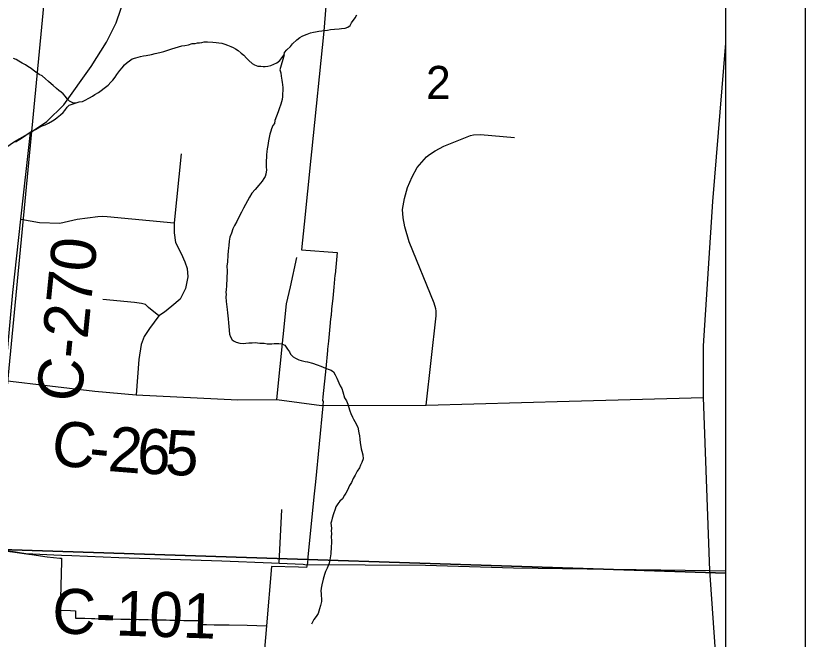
# Model space of a CAD drawing. Extents: x 0 to 34, y -3.9 to 26.2.
# Drawn here: x 8.005 to 9, y 17.653 to 18.439 of the extents above; entities that cross this region are included whole.
import ezdxf

# ---------------------------------------------------------------- set-up
doc = ezdxf.new("R2010")
doc.units = 0
for name, color, linetype in [('GM_X_City_Street', 7, 'Continuous'), ('GM_X_Corporation', 7, 'Continuous'), ('GM_X_County_Road', 7, 'Continuous'), ('GM_X_County_Road_Text', 7, 'Continuous'), ('GM_X_Interchange_Ramps', 7, 'Continuous'), ('GM_X_Interstate_Route', 7, 'Continuous'), ('GM_X_Minor_River', 7, 'Continuous'), ('GM_X_Section', 7, 'Continuous'), ('GM_X_Section_Text', 7, 'Continuous'), ('GM_X_State_Route', 7, 'Continuous'), ('GM_X_State_Shield', 7, 'Continuous'), ('GM_X_Township_Road', 7, 'Continuous'), ('GM_X_US_Route', 7, 'Continuous'), ('SH_Data', 7, 'Continuous')]:
    doc.layers.add(name, color=color, linetype=linetype)

msp = doc.modelspace()

# ---------------------------------------------------------------- linework, layer by layer
at = {"layer": 'GM_X_City_Street'}
for points in [[(8.84586, 17.14096), (8.85864, 17.29642), (8.87165, 17.44975), (8.88717, 17.59506), (8.8882, 17.61025), (8.88771, 17.62546), (8.87968, 17.73906), (8.87166, 17.95722), (8.8717, 18.0226), (8.88372, 18.20449), (8.9, 18.40434)], [(8.52207, 17.94781), (8.53473, 18.0605), (8.53484, 18.06657), (8.5342, 18.06905), (8.53199, 18.07651), (8.50072, 18.15386), (8.49529, 18.17269), (8.49294, 18.18384), (8.49228, 18.19441), (8.49487, 18.20833), (8.49852, 18.22236), (8.50432, 18.23569), (8.51077, 18.24758), (8.5224, 18.26106), (8.52623, 18.26397), (8.53335, 18.26852), (8.5443, 18.27436), (8.57805, 18.2877), (8.58177, 18.28853), (8.59052, 18.28913), (8.63336, 18.28533)], [(8.38989, 17.94749), (8.52207, 17.94781), (8.70219, 17.95261), (8.87166, 17.95722)]]:
    msp.add_lwpolyline(points, dxfattribs=at)
at = {"layer": 'GM_X_Corporation'}
msp.add_lwpolyline([(7.97593, 17.76602), (8.02098, 17.75998), (8.02473, 17.75943), (8.04428, 17.75659), (8.06008, 17.75471), (8.06218, 17.7547), (8.06206, 17.75042), (8.0607, 17.68903), (8.0736, 17.68867), (8.0799, 17.68833), (8.07981, 17.67916), (8.09155, 17.6789), (8.09986, 17.67872), (8.10294, 17.67865), (8.10403, 17.67863), (8.11434, 17.6784), (8.12517, 17.67818), (8.12573, 17.67817), (8.12685, 17.67814), (8.13712, 17.67793), (8.14608, 17.67775), (8.1486, 17.67769), (8.15989, 17.67746), (8.15999, 17.67746), (8.1713, 17.67722), (8.1756, 17.67714), (8.1827, 17.677), (8.19409, 17.67678), (8.19897, 17.67668), (8.20557, 17.67655), (8.21657, 17.67634), (8.21737, 17.67633), (8.22865, 17.67611), (8.23631, 17.67597), (8.23587, 17.67125), (8.245, 17.67108), (8.2548, 17.67089), (8.27374, 17.67053), (8.29646, 17.67009), (8.3209, 17.66962), (8.3163, 17.62008)], dxfattribs=at)
at = {"layer": 'GM_X_County_Road'}
msp.add_line((8.05239, 17.75879), (8.06226, 17.75843), dxfattribs=at)
for points in [[(7.97882, 17.85389), (7.98298, 17.89766), (7.99054, 17.97885), (8.00088, 18.08971), (8.01097, 18.18218), (8.02289, 18.29142)], [(7.99054, 17.97885), (8.10442, 17.96538), (8.1565, 17.96059), (8.28442, 17.95461), (8.33391, 17.95501), (8.38989, 17.94749)], [(7.97496, 17.7675), (8.01738, 17.76076), (8.05239, 17.75879)], [(8.06226, 17.75843), (8.07509, 17.75797), (8.13443, 17.75566), (8.26448, 17.75156), (8.3269, 17.74903)], [(8.3269, 17.74903), (8.33666, 17.74864), (8.36701, 17.74706)], [(8.36701, 17.74706), (8.36904, 17.74695), (8.52111, 17.74613), (8.63208, 17.74268), (8.87968, 17.73906), (8.9, 17.7386)]]:
    msp.add_lwpolyline(points, dxfattribs=at)
at = {"layer": 'GM_X_Interchange_Ramps'}
for points in [[(8.9, 14.1), (8.9, 20.3498)], [(8.39555, 18.45075), (8.39288, 18.4195), (8.37735, 18.26702), (8.37656, 18.25922), (8.36815, 18.17603), (8.36483, 18.14349), (8.40965, 18.14009), (8.4071, 18.11271), (8.407, 18.11173), (8.40548, 18.09636), (8.40414, 18.08268), (8.40277, 18.06879), (8.40203, 18.061), (8.4019, 18.0597), (8.40116, 18.05226), (8.40108, 18.05142), (8.39879, 18.02837), (8.39776, 18.01814), (8.3976, 18.01662), (8.39532, 17.99404), (8.39175, 17.95834), (8.39124, 17.95308), (8.39235, 17.95307), (8.39175, 17.94698), (8.38239, 17.85103), (8.38087, 17.83572), (8.3776, 17.80282), (8.37544, 17.78108), (8.373, 17.7565), (8.37282, 17.75466), (8.37225, 17.74894), (8.37134, 17.74317), (8.36107, 17.74338), (8.32712, 17.74408), (8.3209, 17.66962), (8.3163, 17.62008)]]:
    msp.add_lwpolyline(points, dxfattribs=at)
at = {"layer": 'GM_X_Interstate_Route'}
msp.add_lwpolyline([(7.88483, 16.82734), (8.17686, 16.79566), (8.1936, 16.79415), (8.25412, 16.7887), (8.32182, 16.7826), (8.87081, 16.7253), (8.8978, 17.01499), (8.9, 17.03332), (8.9, 20.9), (3.19894, 20.9)], dxfattribs=at)
at = {"layer": 'GM_X_Minor_River'}
for points in [[(8.04586, 18.30325), (8.05097, 18.30647), (8.0541, 18.30825), (8.05686, 18.31042), (8.06084, 18.31407), (8.0644, 18.31697), (8.06642, 18.31955), (8.06926, 18.32362), (8.07166, 18.32619), (8.08057, 18.32888), (8.08445, 18.33024), (8.08868, 18.33083), (8.0914, 18.33187), (8.09766, 18.33542), (8.10119, 18.33756), (8.10432, 18.33934), (8.10865, 18.34221), (8.11219, 18.34473), (8.11613, 18.34762), (8.12087, 18.35123), (8.12446, 18.35489), (8.12686, 18.35746), (8.12971, 18.36153), (8.13214, 18.36486), (8.13578, 18.36966), (8.13859, 18.37297), (8.14182, 18.37703), (8.145, 18.37994), (8.14814, 18.3821), (8.15131, 18.38463), (8.15595, 18.38597), (8.15904, 18.38661), (8.16174, 18.38726), (8.1656, 18.38825), (8.16907, 18.38887), (8.17562, 18.39013), (8.18025, 18.39109), (8.18604, 18.39238), (8.19106, 18.3937), (8.20114, 18.3971), (8.21391, 18.40078), (8.21776, 18.40139), (8.22239, 18.40234), (8.22703, 18.40368), (8.23086, 18.40391), (8.23357, 18.40456), (8.23626, 18.40483), (8.23932, 18.40509), (8.24203, 18.40575), (8.24624, 18.40596), (8.25311, 18.40568), (8.25729, 18.40514), (8.26071, 18.40462), (8.26451, 18.40409), (8.26829, 18.4028), (8.27169, 18.4019), (8.27583, 18.40022), (8.27845, 18.39897), (8.28143, 18.39695), (8.28516, 18.3949), (8.28886, 18.39171), (8.2922, 18.38929), (8.29547, 18.38536), (8.29842, 18.38258), (8.30246, 18.37861), (8.30545, 18.37697), (8.30997, 18.37527), (8.3134, 18.37514), (8.31644, 18.37464), (8.31913, 18.37491), (8.32258, 18.37515), (8.32606, 18.37615), (8.33385, 18.37965), (8.33741, 18.38255), (8.33985, 18.38587), (8.34306, 18.38955), (8.34357, 18.39257), (8.34638, 18.39589), (8.35075, 18.39989), (8.35358, 18.40359), (8.35874, 18.40832), (8.36269, 18.41121), (8.36582, 18.41299), (8.36855, 18.4144), (8.37205, 18.41578), (8.37631, 18.41713), (8.37979, 18.41814), (8.38248, 18.41841), (8.38673, 18.41938), (8.39058, 18.41999), (8.39326, 18.42026), (8.39749, 18.42085), (8.40134, 18.42146), (8.40634, 18.42202), (8.41247, 18.42254), (8.41516, 18.42281), (8.41977, 18.42339), (8.42326, 18.42439), (8.42602, 18.42656), (8.42769, 18.42992), (8.43254, 18.4362)], [(8.43254, 18.4362), (8.4346, 18.43992)], [(8.34306, 18.38955), (8.33769, 18.37075), (8.33868, 18.3669), (8.33927, 18.3627), (8.34021, 18.35771), (8.34047, 18.35466), (8.34074, 18.35199), (8.34133, 18.34778), (8.34089, 18.33715), (8.34035, 18.33336), (8.33896, 18.32733), (8.3368, 18.32133), (8.3355, 18.31758), (8.33122, 18.30672), (8.33068, 18.30294), (8.32866, 18.30036), (8.32697, 18.29624), (8.32608, 18.29323), (8.32478, 18.28948), (8.32329, 18.28117), (8.32227, 18.27513), (8.32133, 18.27098), (8.32119, 18.26757), (8.32064, 18.2634), (8.3202, 18.25277), (8.32038, 18.24782), (8.32062, 18.24439), (8.32002, 18.23909), (8.31913, 18.23608), (8.31749, 18.23348), (8.31506, 18.23015), (8.31104, 18.22537), (8.30622, 18.21985), (8.3022, 18.21507), (8.29933, 18.21024), (8.29148, 18.1961), (8.28898, 18.19125), (8.28608, 18.18567), (8.28314, 18.17932), (8.28025, 18.17411), (8.27817, 18.17), (8.27642, 18.16475), (8.27429, 18.15951), (8.27371, 18.15459), (8.2731, 18.14929), (8.27244, 18.14247), (8.27182, 18.13678), (8.27148, 18.12843), (8.27088, 18.12313), (8.27101, 18.11704), (8.27024, 18.09843), (8.27002, 18.09312), (8.26951, 18.0901), (8.26978, 18.08742), (8.26928, 18.0844), (8.26979, 18.07829), (8.27091, 18.06836), (8.2715, 18.06415), (8.27211, 18.06032), (8.27233, 18.05651), (8.27289, 18.05155), (8.27308, 18.04697), (8.27422, 18.03742), (8.27522, 18.03396), (8.27736, 18.03007), (8.27997, 18.02844), (8.28259, 18.0272), (8.28712, 18.02588), (8.2917, 18.02569), (8.29477, 18.02595), (8.29822, 18.02619), (8.30282, 18.02639), (8.30665, 18.02662), (8.30932, 18.02651), (8.31236, 18.02601), (8.3177, 18.0258), (8.32151, 18.02527), (8.32761, 18.02502), (8.3303, 18.0253), (8.33337, 18.02556), (8.33642, 18.02543), (8.33946, 18.02493), (8.34398, 18.02323), (8.34723, 18.01854), (8.34976, 18.01501), (8.35116, 18.01192), (8.35447, 18.00874), (8.35708, 18.00712), (8.36158, 18.00503), (8.36422, 18.00417), (8.36952, 18.00282), (8.37256, 18.00232), (8.3786, 18.00056), (8.38463, 17.99841), (8.38915, 17.99671), (8.39516, 17.99419), (8.39969, 17.99287), (8.40233, 17.992), (8.40529, 17.9896), (8.40744, 17.9861), (8.40956, 17.98183)], [(8.07982, 18.32865), (8.07637, 18.32904), (8.07225, 18.33111), (8.06932, 18.33427), (8.06714, 18.33702), (8.06421, 18.34018), (8.06163, 18.34256), (8.05866, 18.34458), (8.05608, 18.34697), (8.05165, 18.35095), (8.04906, 18.35295), (8.04574, 18.35575), (8.04206, 18.35932), (8.03762, 18.36292), (8.03387, 18.36459), (8.02979, 18.36779), (8.02645, 18.37021), (8.02386, 18.37221), (8.01976, 18.37466), (8.01679, 18.37706), (8.01268, 18.37913), (8.00857, 18.38157), (8.00483, 18.38362), (8.00183, 18.38488)], [(8.00398, 18.27982), (8.00948, 18.2834), (8.01419, 18.28626), (8.01734, 18.28842), (8.02009, 18.29021), (8.02401, 18.29271), (8.02948, 18.29554), (8.03341, 18.29804), (8.0377, 18.30015), (8.04157, 18.30114), (8.04586, 18.30325)], [(8.40956, 17.98183), (8.412, 17.97602), (8.41375, 17.97215), (8.41552, 17.96866), (8.41687, 17.96442), (8.41924, 17.9571), (8.42138, 17.95321), (8.42311, 17.94896), (8.42413, 17.94587), (8.42582, 17.94048), (8.42722, 17.93739), (8.42894, 17.93275), (8.43036, 17.93003), (8.43215, 17.92692), (8.43568, 17.91993), (8.43729, 17.91264), (8.43791, 17.90919), (8.4385, 17.90499), (8.4387, 17.90042), (8.43964, 17.89543), (8.43991, 17.89276), (8.44093, 17.88968), (8.44227, 17.88506), (8.44245, 17.88011), (8.44072, 17.87523), (8.43905, 17.87188), (8.43776, 17.8685), (8.43492, 17.86443), (8.43242, 17.85959), (8.42994, 17.85512), (8.42783, 17.85026), (8.42539, 17.84656), (8.42284, 17.84057), (8.42078, 17.83685), (8.41914, 17.83425), (8.41666, 17.82979), (8.41309, 17.82651), (8.41066, 17.82318), (8.40821, 17.81948), (8.40732, 17.81647), (8.40516, 17.81047), (8.40342, 17.80522), (8.4025, 17.80145), (8.402, 17.79881), (8.40228, 17.79613), (8.4025, 17.79232), (8.40238, 17.78928), (8.40262, 17.78585), (8.40243, 17.7813), (8.40264, 17.7771), (8.40251, 17.77407), (8.40231, 17.76913), (8.40195, 17.7604), (8.40049, 17.75285), (8.39954, 17.74832), (8.397, 17.74234), (8.39528, 17.73784), (8.39398, 17.73409), (8.39222, 17.72846), (8.3904, 17.7213), (8.38944, 17.71678), (8.38929, 17.71298), (8.38956, 17.71031), (8.38982, 17.70725), (8.39006, 17.70382), (8.3899, 17.70003), (8.38893, 17.69512), (8.38761, 17.69099), (8.38584, 17.68497), (8.38339, 17.68127), (8.38056, 17.67758), (8.37851, 17.67424), (8.37764, 17.67161)]]:
    msp.add_lwpolyline(points, dxfattribs=at)
at = {"layer": 'GM_X_Section'}
msp.add_lwpolyline([(7.12087, 18.93735), (8.06934, 18.76306), (7.97336, 17.76616), (7.01847, 17.92749)], close=True, dxfattribs=at)
at = {"layer": 'GM_X_State_Route'}
for points in [[(8.02289, 18.29142), (8.04364, 18.30529), (8.06512, 18.32636), (8.09965, 18.37497), (8.11891, 18.40565), (8.13105, 18.42981), (8.14249, 18.46352), (8.19078, 18.64296)], [(7.8763, 18.09977), (7.88982, 18.14772), (7.90335, 18.18551), (7.92146, 18.21586), (7.94339, 18.23843), (7.97949, 18.26414), (8.00301, 18.28017), (8.02289, 18.29142)]]:
    msp.add_lwpolyline(points, dxfattribs=at)
at = {"layer": 'GM_X_State_Shield'}
for points in [[(8.9, 17.73596), (8.9, 18.80132), (8.06934, 18.76306), (7.97336, 17.76616)], [(8.9, 16.98234), (8.9, 17.73596), (7.97336, 17.76616), (7.88639, 16.83202), (8.8743, 16.72579)]]:
    msp.add_lwpolyline(points, close=True, dxfattribs=at)
at = {"layer": 'GM_X_Township_Road'}
msp.add_line((8.33666, 17.74864), (8.34018, 17.81601), dxfattribs=at)
for points in [[(8.21327, 18.26465), (8.20444, 18.17755), (8.20444, 18.16525), (8.2058, 18.15277), (8.21298, 18.139), (8.21777, 18.12842), (8.22056, 18.12004), (8.22156, 18.10967), (8.21857, 18.0947), (8.21178, 18.08153), (8.20148, 18.07247), (8.19203, 18.06496), (8.18484, 18.06057), (8.17327, 18.04461), (8.16648, 18.03443), (8.16269, 18.02405), (8.1599, 18.00529), (8.1565, 17.96059)], [(8.01097, 18.18218), (8.03426, 18.17816), (8.05992, 18.17731), (8.08187, 18.1825), (8.10781, 18.18552), (8.11428, 18.18607), (8.11959, 18.18569), (8.20444, 18.17755)], [(8.33391, 17.95501), (8.34589, 18.07554), (8.35107, 18.09709), (8.35906, 18.13381)], [(8.18484, 18.06057), (8.17207, 18.07095), (8.16808, 18.07455), (8.16289, 18.07614), (8.15411, 18.07734), (8.1142, 18.08093)]]:
    msp.add_lwpolyline(points, dxfattribs=at)
at = {"layer": 'GM_X_US_Route'}
for points in [[(8.02289, 18.29142), (8.04364, 18.30529), (8.06512, 18.32636), (8.09965, 18.37497), (8.11891, 18.40565), (8.13105, 18.42981), (8.14249, 18.46352), (8.19078, 18.64296)], [(7.8763, 18.09977), (7.88982, 18.14772), (7.90335, 18.18551), (7.92146, 18.21586), (7.94339, 18.23843), (7.97949, 18.26414), (8.00301, 18.28017), (8.02289, 18.29142)]]:
    msp.add_lwpolyline(points, dxfattribs=at)
at = {"layer": 'SH_Data'}
msp.add_line((9, 21), (9, 14), dxfattribs=at)

# ---------------------------------------------------------------- texts
at = {"layer": 'GM_X_County_Road_Text'}
for s, height, rotation, p in [('C-270', 0.056818, 84.25836, (8.08687, 17.95032)), ('C', 0.05682, 352.75226, (8.04733, 17.87339)), ('2', 0.05682, 355.42903, (8.11971, 17.86481)), ('6', 0.05682, 357.10521, (8.15641, 17.86191)), ('5', 0.05682, 357.48652, (8.19178, 17.86012)), ('-', 0.05682, 354.12039, (8.09509, 17.86733)), ('C-101', 0.056818, 358.07235, (8.04979, 17.66012))]:
    msp.add_text(s, height=height, rotation=rotation, dxfattribs=at).set_placement(p)
at = {"layer": 'GM_X_Section_Text'}
msp.add_text('2', height=0.04186, rotation=0.00001, dxfattribs=at).set_placement((8.52185, 18.33372))

doc.saveas('drawing.dxf')
